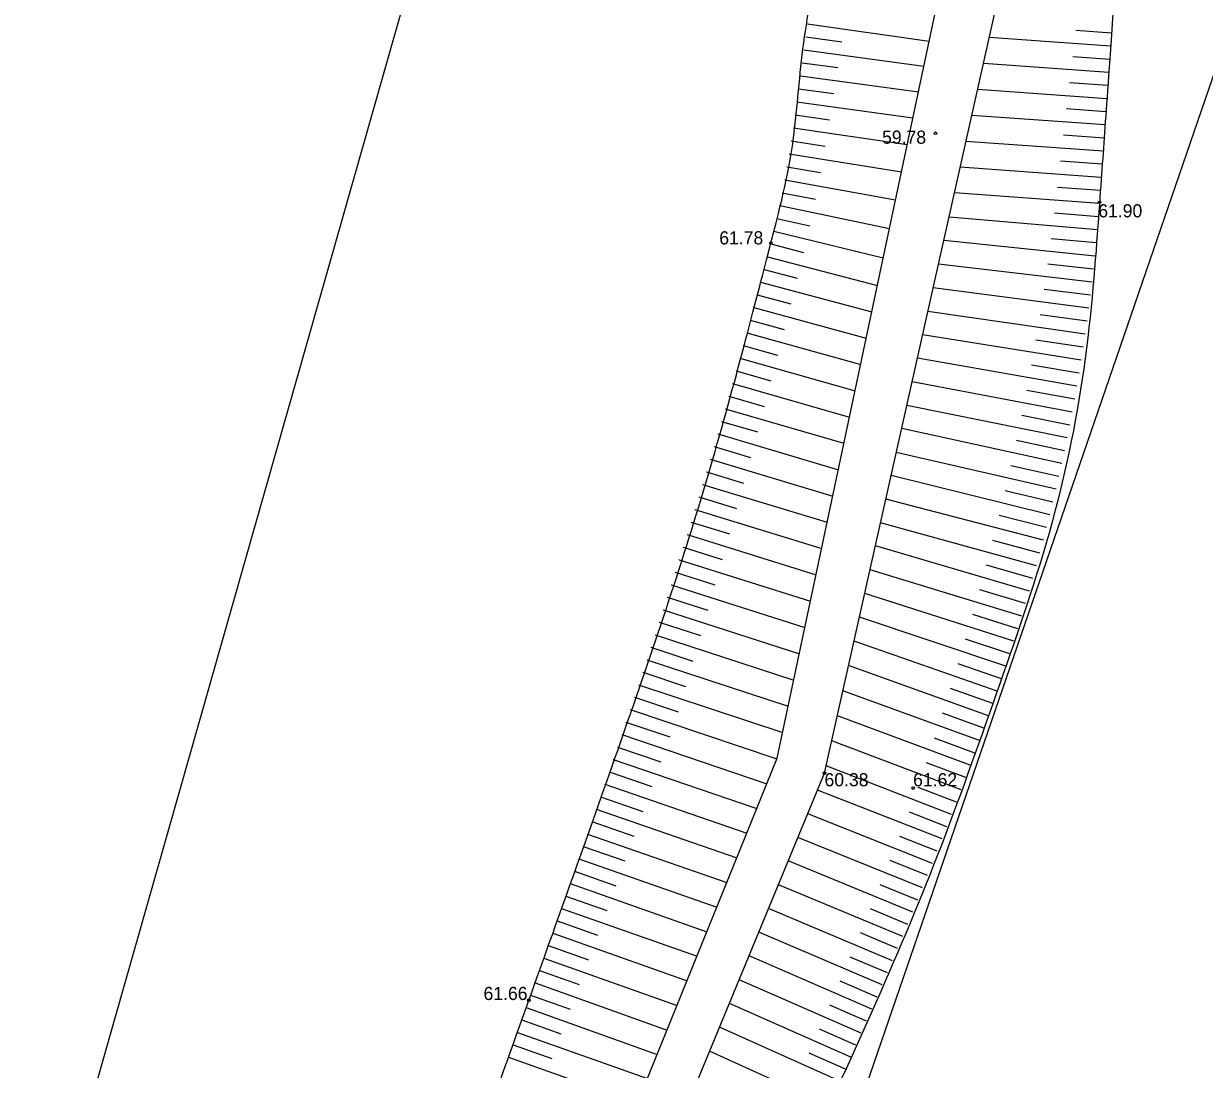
# Model space of a CAD drawing. Extents: x 616607 to 617499, y 408385 to 409695.
# Drawn here: x 617157.32 to 617202.23, y 409004.5 to 409044.26 of the extents above; entities that cross this region are included whole.
import ezdxf

# ---------------------------------------------------------------- set-up
doc = ezdxf.new("R2010")
doc.units = 0
for name, color, linetype in [('HIDG_GRAV_####_####_#', 7, 'Continuous'), ('RAMI_UZMR_####_####_#', 7, 'Continuous'), ('RELJ_AATZ_####_TKST_#', 7, 'Continuous'), ('RELJ_ELEM_####_####_#', 7, 'Continuous'), ('RELJ_NOGA_####_####_#', 7, 'Continuous')]:
    doc.layers.add(name, color=color, linetype=linetype)

# ---------------------------------------------------------------- blocks, each defined once
blk = doc.blocks.new('PKT')
at = {"layer": 'RELJ_ELEM_####_####_#'}
blk.add_circle((0, 0), 0.05, dxfattribs=at)

msp = doc.modelspace()

# ---------------------------------------------------------------- linework, layer by layer
at = {"layer": 'HIDG_GRAV_####_####_#'}
for points in [[(617165.749, 408966.38), (617185.985, 409016.335), (617192.341, 409046.347)], [(617167.163, 408965.849), (617187.78, 409015.761), (617194.535, 409045.934)]]:
    msp.add_lwpolyline(points, dxfattribs=at)
at = {"layer": 'RAMI_UZMR_####_####_#'}
msp.add_lwpolyline([(617101.571, 408748.246), (617213.472, 409074.039), (617215.883, 409140.56), (617165.121, 409241.478), (617252.137, 409353.424), (617269.572, 409425.099), (617332.631, 409510.312), (617439.945, 409622.037), (617425.373, 409635.959), (617242.079, 409440.82), (617216.614, 409355.716), (617136.613, 409246.751), (617191.828, 409115.62), (617145.545, 408952.8)], dxfattribs=at)
at = {"layer": 'RELJ_NOGA_####_####_#'}
for p, q in [((617187.135, 409044.262), (617187.134, 409044.262)), ((617187.135, 409044.262), (617191.758, 409043.593)), ((617187.135, 409044.262), (617187.136, 409044.262)), ((617198.697, 409043.904), (617197.333, 409044.001)), ((617187.065, 409043.767), (617187.064, 409043.767)), ((617187.065, 409043.767), (617188.442, 409043.573)), ((617187.065, 409043.767), (617187.065, 409043.767)), ((617198.661, 409043.405), (617194.042, 409043.734)), ((617186.996, 409043.272), (617186.995, 409043.272)), ((617186.996, 409043.272), (617191.556, 409042.642)), ((617186.996, 409043.272), (617186.997, 409043.272)), ((617198.626, 409042.906), (617197.217, 409043.006)), ((617186.928, 409042.776), (617188.286, 409042.592)), ((617186.928, 409042.776), (617186.928, 409042.776)), ((617186.928, 409042.776), (617186.929, 409042.776)), ((617198.59, 409042.407), (617193.822, 409042.747)), ((617186.862, 409042.281), (617186.861, 409042.281)), ((617186.862, 409042.281), (617191.352, 409041.676)), ((617186.862, 409042.281), (617186.863, 409042.281)), ((617198.555, 409041.909), (617197.101, 409042.012)), ((617186.795, 409041.785), (617186.794, 409041.785)), ((617186.795, 409041.785), (617188.13, 409041.604)), ((617186.795, 409041.785), (617186.795, 409041.785)), ((617198.519, 409041.41), (617193.601, 409041.76)), ((617186.727, 409041.29), (617186.726, 409041.29)), ((617186.727, 409041.29), (617191.141, 409040.682)), ((617186.727, 409041.29), (617186.728, 409041.29)), ((617186.658, 409040.795), (617187.971, 409040.611)), ((617186.658, 409040.795), (617186.658, 409040.795)), ((617186.658, 409040.795), (617186.658, 409040.795)), ((617198.448, 409040.412), (617193.38, 409040.773)), ((617198.484, 409040.911), (617196.986, 409041.018)), ((617186.587, 409040.3), (617186.586, 409040.3)), ((617186.587, 409040.3), (617190.925, 409039.662)), ((617186.587, 409040.3), (617186.588, 409040.3)), ((617186.513, 409039.805), (617186.512, 409039.805)), ((617186.513, 409039.805), (617187.804, 409039.608)), ((617186.513, 409039.805), (617186.513, 409039.805)), ((617198.377, 409039.415), (617193.159, 409039.786)), ((617198.412, 409039.914), (617196.87, 409040.023)), ((617186.435, 409039.311), (617186.434, 409039.311)), ((617186.435, 409039.311), (617190.706, 409038.629)), ((617186.435, 409039.311), (617186.436, 409039.311)), ((617198.341, 409038.916), (617196.754, 409039.029)), ((617186.353, 409038.818), (617187.626, 409038.603)), ((617186.353, 409038.818), (617186.353, 409038.818)), ((617186.353, 409038.818), (617186.354, 409038.818)), ((617198.306, 409038.417), (617192.938, 409038.8)), ((617186.266, 409038.326), (617186.265, 409038.326)), ((617186.266, 409038.326), (617190.482, 409037.567)), ((617186.266, 409038.326), (617186.267, 409038.326)), ((617198.27, 409037.919), (617196.638, 409038.035)), ((617186.174, 409037.834), (617186.173, 409037.834)), ((617186.174, 409037.834), (617187.431, 409037.589)), ((617186.174, 409037.834), (617186.174, 409037.834)), ((617198.235, 409037.42), (617192.72, 409037.825)), ((617186.075, 409037.344), (617186.074, 409037.344)), ((617186.075, 409037.344), (617190.251, 409036.478)), ((617186.075, 409037.344), (617186.076, 409037.344)), ((617185.969, 409036.856), (617187.218, 409036.573)), ((617185.969, 409036.856), (617185.969, 409036.856)), ((617185.969, 409036.856), (617185.969, 409036.856)), ((617198.156, 409036.423), (617192.515, 409036.909)), ((617198.197, 409036.921), (617196.522, 409037.052)), ((617185.855, 409036.369), (617185.854, 409036.369)), ((617185.855, 409036.369), (617190.013, 409035.356)), ((617185.855, 409036.369), (617185.856, 409036.368)), ((617185.733, 409035.884), (617186.982, 409035.558)), ((617185.733, 409035.884), (617185.733, 409035.884)), ((617185.733, 409035.884), (617185.734, 409035.884)), ((617198.062, 409035.427), (617192.315, 409036.016)), ((617198.111, 409035.925), (617196.402, 409036.086)), ((617185.607, 409035.4), (617185.606, 409035.4)), ((617185.607, 409035.4), (617189.79, 409034.3)), ((617185.607, 409035.4), (617185.608, 409035.4)), ((617185.48, 409034.916), (617185.479, 409034.917)), ((617185.48, 409034.916), (617186.741, 409034.582)), ((617185.48, 409034.916), (617185.48, 409034.916)), ((617197.955, 409034.433), (617192.114, 409035.12)), ((617198.01, 409034.93), (617196.272, 409035.122)), ((617185.351, 409034.433), (617185.35, 409034.434)), ((617185.351, 409034.433), (617189.579, 409033.305)), ((617185.351, 409034.433), (617185.352, 409034.433)), ((617185.221, 409033.95), (617185.221, 409033.951)), ((617185.221, 409033.95), (617186.497, 409033.607)), ((617185.221, 409033.95), (617185.221, 409033.95)), ((617197.832, 409033.441), (617191.913, 409034.221)), ((617197.895, 409033.937), (617196.131, 409034.157)), ((617185.09, 409033.468), (617185.089, 409033.468)), ((617185.09, 409033.468), (617189.366, 409032.3)), ((617185.09, 409033.468), (617185.091, 409033.468)), ((617197.696, 409032.45), (617191.711, 409033.319)), ((617197.766, 409032.945), (617195.98, 409033.193)), ((617184.958, 409032.986), (617186.249, 409032.631)), ((617184.958, 409032.986), (617184.958, 409032.986)), ((617184.958, 409032.986), (617184.958, 409032.986)), ((617184.825, 409032.504), (617184.824, 409032.504)), ((617184.825, 409032.504), (617189.155, 409031.304)), ((617184.825, 409032.504), (617184.826, 409032.504)), ((617197.545, 409031.462), (617191.512, 409032.431)), ((617197.622, 409031.956), (617195.818, 409032.229)), ((617184.69, 409032.022), (617185.998, 409031.657)), ((617184.69, 409032.022), (617184.69, 409032.022)), ((617184.69, 409032.022), (617184.691, 409032.022)), ((617184.555, 409031.541), (617184.554, 409031.541)), ((617184.555, 409031.541), (617188.943, 409030.303)), ((617184.555, 409031.541), (617184.556, 409031.541)), ((617197.38, 409030.475), (617191.312, 409031.537)), ((617197.464, 409030.968), (617195.648, 409031.271)), ((617184.419, 409031.06), (617184.418, 409031.06)), ((617184.419, 409031.06), (617185.744, 409030.683)), ((617184.419, 409031.06), (617184.419, 409031.06)), ((617184.281, 409030.579), (617184.28, 409030.579)), ((617184.281, 409030.579), (617188.731, 409029.3)), ((617184.281, 409030.579), (617184.282, 409030.579)), ((617197.202, 409029.491), (617191.111, 409030.638)), ((617184.142, 409030.099), (617185.487, 409029.71)), ((617184.142, 409030.099), (617184.142, 409030.099)), ((617184.142, 409030.099), (617184.143, 409030.099)), ((617197.293, 409029.983), (617195.468, 409030.312)), ((617184.003, 409029.619), (617184.002, 409029.619)), ((617184.003, 409029.619), (617188.52, 409028.304)), ((617184.003, 409029.619), (617184.004, 409029.618)), ((617197.009, 409028.51), (617190.91, 409029.741)), ((617183.862, 409029.139), (617185.227, 409028.736)), ((617183.862, 409029.139), (617183.862, 409029.139)), ((617183.862, 409029.139), (617183.862, 409029.139)), ((617197.107, 409029), (617195.279, 409029.361)), ((617183.72, 409028.659), (617183.719, 409028.66)), ((617183.72, 409028.659), (617188.307, 409027.297)), ((617183.72, 409028.659), (617183.721, 409028.659)), ((617196.803, 409027.532), (617190.714, 409028.868)), ((617183.578, 409028.18), (617184.965, 409027.765)), ((617183.578, 409028.18), (617183.578, 409028.18)), ((617183.578, 409028.18), (617183.578, 409028.18)), ((617196.907, 409028.021), (617195.079, 409028.406)), ((617183.434, 409027.701), (617183.433, 409027.701)), ((617183.434, 409027.701), (617188.095, 409026.295)), ((617183.434, 409027.701), (617183.435, 409027.701)), ((617196.583, 409026.556), (617190.511, 409027.961)), ((617183.29, 409027.222), (617183.29, 409027.223)), ((617183.29, 409027.222), (617184.699, 409026.794)), ((617183.29, 409027.222), (617183.29, 409027.222)), ((617196.694, 409027.044), (617194.869, 409027.452)), ((617183.144, 409026.744), (617187.884, 409025.303)), ((617183.144, 409026.744), (617183.144, 409026.744)), ((617183.144, 409026.744), (617183.145, 409026.744)), ((617196.349, 409025.584), (617190.316, 409027.086)), ((617196.468, 409026.07), (617194.651, 409026.503)), ((617182.998, 409026.266), (617184.432, 409025.826)), ((617182.998, 409026.266), (617182.998, 409026.266)), ((617182.998, 409026.266), (617182.998, 409026.266)), ((617196.102, 409024.615), (617190.113, 409026.179)), ((617182.851, 409025.788), (617182.85, 409025.788)), ((617182.851, 409025.788), (617187.672, 409024.3)), ((617182.851, 409025.788), (617182.852, 409025.788)), ((617196.227, 409025.099), (617194.424, 409025.559)), ((617182.703, 409025.31), (617182.703, 409025.311)), ((617182.703, 409025.31), (617184.162, 409024.856)), ((617182.703, 409025.31), (617182.703, 409025.31)), ((617195.842, 409023.649), (617189.912, 409025.284)), ((617182.554, 409024.833), (617182.553, 409024.833)), ((617182.554, 409024.833), (617187.46, 409023.299)), ((617182.554, 409024.833), (617182.555, 409024.833)), ((617195.974, 409024.132), (617194.186, 409024.613)), ((617182.404, 409024.356), (617183.89, 409023.89)), ((617182.404, 409024.356), (617182.404, 409024.356)), ((617182.404, 409024.356), (617182.405, 409024.356)), ((617195.569, 409022.687), (617189.715, 409024.402)), ((617182.254, 409023.879), (617182.253, 409023.88)), ((617182.254, 409023.879), (617187.248, 409022.296)), ((617182.254, 409023.879), (617182.255, 409023.879)), ((617195.707, 409023.168), (617193.939, 409023.671)), ((617182.103, 409023.403), (617182.102, 409023.403)), ((617182.103, 409023.403), (617183.614, 409022.921)), ((617182.103, 409023.403), (617182.103, 409023.403)), ((617195.282, 409021.729), (617189.512, 409023.497)), ((617181.95, 409022.926), (617181.95, 409022.927)), ((617181.95, 409022.926), (617187.037, 409021.299)), ((617181.95, 409022.926), (617181.951, 409022.926)), ((617195.427, 409022.208), (617193.683, 409022.731)), ((617181.798, 409022.45), (617181.797, 409022.45)), ((617181.798, 409022.45), (617183.338, 409021.955)), ((617181.798, 409022.45), (617181.798, 409022.45)), ((617194.983, 409020.775), (617189.309, 409022.592)), ((617181.644, 409021.975), (617181.643, 409021.975)), ((617181.644, 409021.975), (617186.825, 409020.301)), ((617181.644, 409021.975), (617181.645, 409021.974)), ((617195.134, 409021.252), (617193.418, 409021.793)), ((617181.49, 409021.499), (617181.489, 409021.499)), ((617181.49, 409021.499), (617183.059, 409020.99)), ((617181.49, 409021.499), (617181.49, 409021.499)), ((617194.671, 409019.825), (617189.107, 409021.687)), ((617181.335, 409021.024), (617181.334, 409021.024)), ((617181.335, 409021.024), (617186.612, 409019.294)), ((617181.335, 409021.024), (617181.336, 409021.023)), ((617181.179, 409020.549), (617182.777, 409020.022)), ((617181.179, 409020.549), (617181.179, 409020.549)), ((617181.179, 409020.549), (617181.179, 409020.548)), ((617194.346, 409018.879), (617188.905, 409020.784)), ((617194.829, 409020.3), (617193.143, 409020.852)), ((617181.023, 409020.074), (617181.022, 409020.074)), ((617181.023, 409020.074), (617186.402, 409018.302)), ((617181.023, 409020.074), (617181.023, 409020.073)), ((617180.865, 409019.599), (617182.495, 409019.06)), ((617180.865, 409019.599), (617180.865, 409019.599)), ((617180.865, 409019.599), (617180.866, 409019.599)), ((617194.012, 409017.937), (617188.695, 409019.849)), ((617194.51, 409019.352), (617192.859, 409019.917)), ((617180.708, 409019.124), (617180.707, 409019.125)), ((617180.708, 409019.124), (617186.19, 409017.301)), ((617180.708, 409019.124), (617180.709, 409019.124)), ((617180.549, 409018.65), (617182.21, 409018.095)), ((617180.549, 409018.65), (617180.549, 409018.65)), ((617180.549, 409018.65), (617180.55, 409018.65)), ((617193.671, 409016.997), (617188.482, 409018.894)), ((617194.18, 409018.408), (617192.566, 409018.981)), ((617180.39, 409018.176), (617180.389, 409018.176)), ((617180.39, 409018.176), (617185.972, 409016.302)), ((617180.39, 409018.176), (617180.391, 409018.176)), ((617193.325, 409016.059), (617188.269, 409017.945)), ((617193.842, 409017.467), (617192.266, 409018.037)), ((617180.231, 409017.702), (617180.23, 409017.702)), ((617180.231, 409017.702), (617181.896, 409017.14)), ((617180.231, 409017.702), (617180.231, 409017.702)), ((617180.071, 409017.229), (617180.07, 409017.229)), ((617180.071, 409017.229), (617185.589, 409015.357)), ((617180.071, 409017.229), (617180.072, 409017.228)), ((617192.973, 409015.123), (617188.056, 409016.994)), ((617193.499, 409016.527), (617191.962, 409017.095)), ((617179.91, 409016.755), (617181.556, 409016.194)), ((617179.91, 409016.755), (617179.91, 409016.755)), ((617179.91, 409016.755), (617179.91, 409016.755)), ((617179.749, 409016.282), (617179.748, 409016.282)), ((617179.749, 409016.282), (617185.21, 409014.421)), ((617179.749, 409016.282), (617179.75, 409016.282)), ((617192.615, 409014.189), (617187.842, 409016.036)), ((617193.15, 409015.59), (617191.654, 409016.155)), ((617179.587, 409015.809), (617181.217, 409015.251)), ((617179.587, 409015.809), (617179.587, 409015.809)), ((617179.587, 409015.809), (617179.587, 409015.809)), ((617179.425, 409015.336), (617179.424, 409015.336)), ((617179.425, 409015.336), (617184.828, 409013.477)), ((617179.425, 409015.336), (617179.426, 409015.335)), ((617192.253, 409013.257), (617187.514, 409015.117)), ((617192.795, 409014.655), (617191.341, 409015.213)), ((617179.262, 409014.863), (617180.874, 409014.306)), ((617179.262, 409014.863), (617179.262, 409014.863)), ((617179.262, 409014.863), (617179.262, 409014.863)), ((617179.099, 409014.39), (617179.098, 409014.391)), ((617179.099, 409014.39), (617184.449, 409012.542)), ((617179.099, 409014.39), (617179.1, 409014.39)), ((617191.885, 409012.327), (617187.141, 409014.214)), ((617192.435, 409013.722), (617191.014, 409014.276)), ((617178.935, 409013.918), (617180.532, 409013.364)), ((617178.935, 409013.918), (617178.935, 409013.918)), ((617178.935, 409013.918), (617178.935, 409013.918)), ((617178.771, 409013.446), (617178.77, 409013.446)), ((617178.771, 409013.446), (617184.067, 409011.6)), ((617178.771, 409013.446), (617178.772, 409013.445)), ((617191.512, 409011.399), (617186.771, 409013.319)), ((617192.069, 409012.791), (617190.647, 409013.354)), ((617178.606, 409012.974), (617180.188, 409012.422)), ((617178.606, 409012.974), (617178.606, 409012.974)), ((617178.606, 409012.974), (617178.607, 409012.973)), ((617178.441, 409012.502), (617183.688, 409010.665)), ((617178.441, 409012.502), (617178.441, 409012.502)), ((617178.441, 409012.502), (617178.442, 409012.501)), ((617191.134, 409010.473), (617186.4, 409012.42)), ((617191.699, 409011.863), (617190.277, 409012.435)), ((617178.276, 409012.03), (617179.843, 409011.479)), ((617178.276, 409012.03), (617178.276, 409012.03)), ((617178.276, 409012.03), (617178.277, 409012.03)), ((617178.11, 409011.558), (617178.109, 409011.558)), ((617178.11, 409011.558), (617183.31, 409009.731)), ((617178.11, 409011.558), (617178.111, 409011.558)), ((617190.752, 409009.549), (617186.028, 409011.518)), ((617191.324, 409010.936), (617189.902, 409011.515)), ((617177.944, 409011.086), (617179.497, 409010.539)), ((617177.944, 409011.086), (617177.944, 409011.086)), ((617177.944, 409011.086), (617177.945, 409011.086)), ((617177.778, 409010.615), (617177.777, 409010.615)), ((617177.778, 409010.615), (617182.931, 409008.797)), ((617177.778, 409010.615), (617177.779, 409010.614)), ((617190.365, 409008.627), (617185.653, 409010.61)), ((617190.944, 409010.011), (617189.524, 409010.597)), ((617177.611, 409010.143), (617177.611, 409010.144)), ((617177.611, 409010.143), (617179.15, 409009.598)), ((617177.611, 409010.143), (617177.612, 409010.143)), ((617177.444, 409009.672), (617177.443, 409009.672)), ((617177.444, 409009.672), (617182.551, 409007.858)), ((617177.444, 409009.672), (617177.445, 409009.672)), ((617189.974, 409007.707), (617185.281, 409009.71)), ((617190.559, 409009.088), (617189.144, 409009.683)), ((617177.277, 409009.201), (617178.803, 409008.659)), ((617177.277, 409009.201), (617177.277, 409009.201)), ((617177.277, 409009.201), (617177.277, 409009.201)), ((617189.578, 409006.788), (617184.911, 409008.814)), ((617177.109, 409008.73), (617177.108, 409008.73)), ((617177.109, 409008.73), (617182.173, 409006.925)), ((617177.109, 409008.73), (617177.11, 409008.73)), ((617190.17, 409008.167), (617188.759, 409008.765)), ((617176.941, 409008.259), (617178.455, 409007.72)), ((617176.941, 409008.259), (617176.941, 409008.259)), ((617176.941, 409008.259), (617176.942, 409008.259)), ((617189.178, 409005.872), (617184.535, 409007.905)), ((617176.773, 409007.788), (617176.772, 409007.788)), ((617176.773, 409007.788), (617181.796, 409005.993)), ((617176.773, 409007.788), (617176.774, 409007.788)), ((617189.776, 409007.247), (617188.373, 409007.853)), ((617176.605, 409007.317), (617178.106, 409006.781)), ((617176.605, 409007.317), (617176.605, 409007.317)), ((617176.605, 409007.317), (617176.605, 409007.317)), ((617188.775, 409004.957), (617184.162, 409007.002)), ((617176.437, 409006.846), (617176.436, 409006.847)), ((617176.437, 409006.846), (617181.421, 409005.067)), ((617176.437, 409006.846), (617176.438, 409006.846)), ((617189.379, 409006.33), (617187.982, 409006.939)), ((617176.269, 409006.375), (617176.268, 409006.376)), ((617176.269, 409006.375), (617177.758, 409005.844)), ((617176.269, 409006.375), (617176.269, 409006.375)), ((617188.368, 409004.043), (617183.788, 409006.097)), ((617176.101, 409005.904), (617176.1, 409005.905)), ((617176.101, 409005.904), (617181.047, 409004.146)), ((617176.101, 409005.904), (617176.102, 409005.904)), ((617188.977, 409005.414), (617187.589, 409006.026)), ((617175.934, 409005.433), (617177.412, 409004.909)), ((617175.934, 409005.433), (617175.934, 409005.433)), ((617175.934, 409005.433), (617175.934, 409005.433)), ((617187.957, 409003.131), (617183.412, 409005.186)), ((617175.767, 409004.962), (617175.766, 409004.962)), ((617175.767, 409004.962), (617180.673, 409003.221)), ((617175.767, 409004.962), (617175.768, 409004.962)), ((617188.572, 409004.5), (617187.193, 409005.115))]:
    msp.add_line(p, q, dxfattribs=at)
for points in [[(617164.214, 408966.743), (617164.067, 408966.559), (617163.746, 408966.808), (617163.516, 408966.861), (617163.258, 408966.92), (617163, 408966.979), (617162.742, 408967.038), (617162.506, 408967.092), (617162.27, 408967.145), (617162.033, 408967.199), (617161.839, 408967.244), (617161.499, 408967.338), (617161.53, 408967.523), (617162.076, 408970.795), (617163.848, 408974.182), (617165.139, 408977.462), (617166.432, 408980.748), (617167.724, 408984.034), (617169.019, 408987.319), (617170.314, 408990.606), (617171.612, 408993.892), (617172.906, 408997.179), (617174.2, 409000.463), (617175.346, 409003.8), (617176.537, 409007.126), (617179.936, 409016.621), (617183.209, 409026.15), (617185.744, 409035.924), (617186.657, 409039.444), (617186.852, 409043.096), (617187.532, 409046.664), (617188.191, 409050.122), (617189.04, 409053.52), (617189.932, 409056.942), (617189.98, 409057.126), (617190.012, 409057.369), (617190.199, 409057.442), (617190.492, 409057.556), (617190.793, 409057.447), (617191.088, 409057.419), (617191.386, 409057.391), (617191.684, 409057.369), (617191.981, 409057.328), (617192.587, 409057.244), (617193.186, 409057.135), (617193.777, 409056.97), (617195.009, 409056.627), (617196.209, 409056.219), (617197.396, 409055.759), (617198.619, 409055.285), (617199.811, 409054.744), (617201.035, 409054.276), (617202.236, 409053.817), (617203.458, 409053.413), (617204.671, 409052.991), (617204.777, 409052.954), (617204.889, 409052.983), (617204.996, 409052.903), (617205.146, 409052.79), (617205.251, 409052.619), (617205.213, 409052.483), (617205.152, 409052.266), (617205.006, 409052.028), (617204.832, 409051.838), (617204.408, 409051.373), (617203.987, 409050.962), (617203.555, 409050.533), (617202.561, 409049.55), (617201.563, 409048.573), (617200.565, 409047.597), (617200.116, 409047.158), (617199.367, 409046.94), (617199.151, 409046.35), (617199.035, 409046.033), (617198.919, 409045.717), (617198.803, 409045.4)], [(617198.803, 409045.4), (617198.615, 409042.755), (617198.427, 409040.111), (617198.238, 409037.467), (617197.787, 409031.121), (617196.45, 409024.852), (617194.315, 409018.79), (617192.146, 409012.632), (617189.639, 409006.739), (617186.922, 409000.869), (617184.173, 408994.931), (617181.194, 408989.114), (617178.515, 408983.149), (617177.185, 408980.188), (617175.902, 408977.208), (617174.699, 408974.191), (617174.102, 408972.692), (617173.577, 408971.168), (617173.022, 408969.656), (617172.469, 408968.151), (617172.801, 408966.435), (617171.55, 408965.074), (617170.839, 408964.299), (617169.714, 408965.108), (617168.821, 408965.3), (617168.683, 408965.329), (617168.544, 408965.359), (617168.405, 408965.389)]]:
    msp.add_open_spline(points, degree=3, dxfattribs=at)

# ---------------------------------------------------------------- block references
at = {"layer": 'RELJ_ELEM_####_####_#'}
for p in [(617191.999, 409040.094), (617198.238, 409037.467), (617185.744, 409035.924), (617187.78, 409015.761), (617191.149, 409015.195), (617176.537, 409007.126)]:
    msp.add_blockref('PKT', p, dxfattribs=at)

# ---------------------------------------------------------------- texts
at = {"layer": 'RELJ_AATZ_####_TKST_#'}
for s, p in [('59.78', (617189.97, 409039.696)), ('61.90', (617198.19, 409036.896)), ('61.78', (617183.777, 409035.868)), ('60.38', (617187.78, 409015.261)), ('61.62', (617191.149, 409015.261)), ('61.66', (617174.813, 409007.133))]:
    msp.add_text(s, height=0.5, dxfattribs=at).set_placement(p)

doc.saveas('drawing.dxf')
